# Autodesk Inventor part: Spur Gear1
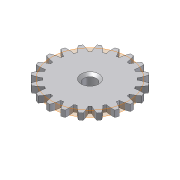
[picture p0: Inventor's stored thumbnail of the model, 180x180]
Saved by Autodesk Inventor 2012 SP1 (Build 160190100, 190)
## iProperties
Created: 2006-09
Part Number: Spur Gear1
Document SubType Name: Modeling
Mass: 15.9162 g
Surface Area: 84.1765 cm^2
Volume: 15.9162 cm^3
Density: 1 g/cm^3
Material: Default
CustomPartVersion: 1
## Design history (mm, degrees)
sketch "Sketch1"
  geometry: C1 r 33 at (0, 0)
  constraints: 1 centre point
  dimensions: "d0" = 66 diameter of C1 (= da_da)
extrude "Extrusion1" new body sketch "Sketch1" distance "d1" = 5 (= da_b); taper "d2" = 0 deg
workplane "Work Plane2"
sketch "Sketch2"
  geometry: C1 r 33 at (0, 0) reference; C2 r 30 at (0, 0)
  constraints: 1 centre point, 1 coincident
  dimensions: "d3" = 60 diameter of C2 (= da_dw)
extrude_surface "ExtrusionSrf1" sketch "Sketch2" dims "d4" = 10, "d5" = 0
workplane "Work Plane8"
workplane "Work Plane9"
feature "Spur Gear" dims "da_b" = 5, "da_d" = 60, "da_aw" = 120, "da_da" = 66, "da_df" = 52.5, "da_dw" = 60, angle "da_beta" = 0 deg, "da_lefttooth" = 0, "da_righttooth" = 0
sketch "Sketch3"
  geometry: C1 r 10 at (0, 0); 1 further point
  constraints: 1 centre point, 1 coincident
  dimensions: "d49" = 20 diameter of C1
extrude "Extrusion2" join sketch "Sketch3" distance "d50" = 10; taper "d51" = 0 deg
sketch "Sketch5"
  geometry: C1 r 5 at (0, 0); 1 further point
  constraints: 1 centre point, 1 coincident
  dimensions: "d53" = 10 diameter of C1
extrude "Extrusion3" cut sketch "Sketch5" stored distance "d54" = 10; taper "d55" = 0 deg
chamfer "Chamfer1" distance "d56" = 2; stored, may be unused: second distance "d57" = 2, angle "d58" = 45 deg
body "Solid1"
body "Srf1"
other parameters: "d17" = 0, "d34" = 9 deg (computed from da_z), "d39" = 0, "d41" = 0, "d47" = 0, "d48" = 0
